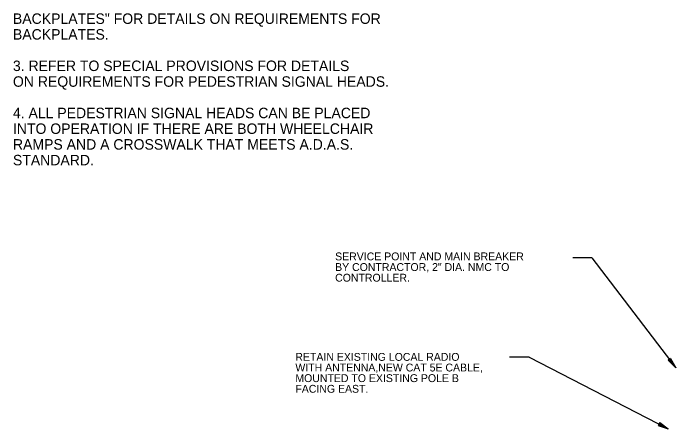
# Model space of a CAD drawing. Extents: x 659404 to 660404, y 642315 to 642955.
# Drawn here: x 659597.4 to 659850.2, y 642628.4 to 642787 of the extents above; entities that cross this region are included whole.
import ezdxf

# ---------------------------------------------------------------- set-up
doc = ezdxf.new("R2010")
doc.units = 0
doc.layers.add('T_Drafting', color=7, linetype='Continuous')
doc.layers.add('T_Notes', color=7, linetype='Continuous')

msp = doc.modelspace()

# ---------------------------------------------------------------- linework, layer by layer
at = {"layer": 'T_Drafting'}
for p, q in [((659818.27, 642693.63), (659810.91, 642693.63)), ((659818.27, 642693.63), (659850.24, 642651.67)), ((659794.26, 642655.68), (659786.73, 642655.68)), ((659794.26, 642655.68), (659847.4, 642628.35)), ((659848.29, 642655.21), (659847.34, 642654.48)), ((659847.34, 642654.48), (659850.24, 642651.67)), ((659847.42, 642654.54), (659849.83, 642652.2)), ((659847.5, 642654.61), (659849.42, 642652.74)), ((659847.58, 642654.67), (659849.01, 642653.27)), ((659847.66, 642654.73), (659848.6, 642653.81)), ((659847.74, 642654.79), (659848.2, 642654.34)), ((659847.89, 642654.9), (659848.2, 642654.34)), ((659847.97, 642654.96), (659848.6, 642653.81)), ((659848.05, 642655.03), (659849.01, 642653.27)), ((659848.13, 642655.09), (659849.42, 642652.74)), ((659848.21, 642655.15), (659849.83, 642652.2)), ((659848.29, 642655.21), (659850.24, 642651.67)), ((659844.12, 642630.72), (659843.57, 642629.65)), ((659843.8, 642630.1), (659844.4, 642629.89)), ((659843.89, 642630.27), (659844.4, 642629.89)), ((659843.93, 642630.36), (659845, 642629.59)), ((659843.98, 642630.45), (659845.6, 642629.28)), ((659844.02, 642630.54), (659846.19, 642628.97)), ((659844.07, 642630.63), (659846.81, 642628.66)), ((659844.12, 642630.72), (659847.4, 642628.35)), ((659843.57, 642629.65), (659847.4, 642628.35)), ((659843.61, 642629.74), (659846.81, 642628.66)), ((659843.66, 642629.83), (659846.19, 642628.97)), ((659843.71, 642629.92), (659845.6, 642629.28)), ((659843.75, 642630.01), (659845, 642629.59))]:
    msp.add_line(p, q, dxfattribs=at)

# ---------------------------------------------------------------- texts
for s, p in [('SERVICE POINT AND MAIN BREAKER', (659720.23, 642692.64)), ('BY CONTRACTOR, 2" DIA. NMC TO', (659720.23, 642688.58)), ('CONTROLLER.', (659720.23, 642684.51)), ('RETAIN EXISTING LOCAL RADIO', (659705.05, 642654.29)), ('WITH ANTENNA,NEW CAT 5E CABLE, ', (659705.05, 642650.23)), ('MOUNTED TO EXISTING POLE B ', (659705.05, 642646.17)), ('FACING EAST.', (659705.05, 642642.1))]:
    msp.add_text(s, height=3, dxfattribs=at).set_placement(p)
at = {"layer": 'T_Notes'}
for s, p in [('BACKPLATES" FOR DETAILS ON REQUIREMENTS FOR ', (659597.24, 642782.9)), ('BACKPLATES.', (659597.24, 642776.9)), ('3. REFER TO SPECIAL PROVISIONS FOR DETAILS', (659597.24, 642764.9)), ('ON REQUIREMENTS FOR PEDESTRIAN SIGNAL HEADS.', (659597.24, 642758.9)), ('4. ALL PEDESTRIAN SIGNAL HEADS CAN BE PLACED', (659597.24, 642746.9)), ('INTO OPERATION IF THERE ARE BOTH WHEELCHAIR', (659597.24, 642740.9)), ('RAMPS AND A CROSSWALK THAT MEETS A.D.A.S.', (659597.24, 642734.9)), ('STANDARD.', (659597.24, 642728.9))]:
    msp.add_text(s, height=4, dxfattribs=at).set_placement(p)

doc.saveas('drawing.dxf')
